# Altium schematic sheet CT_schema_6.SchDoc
size 274 x 160 mm
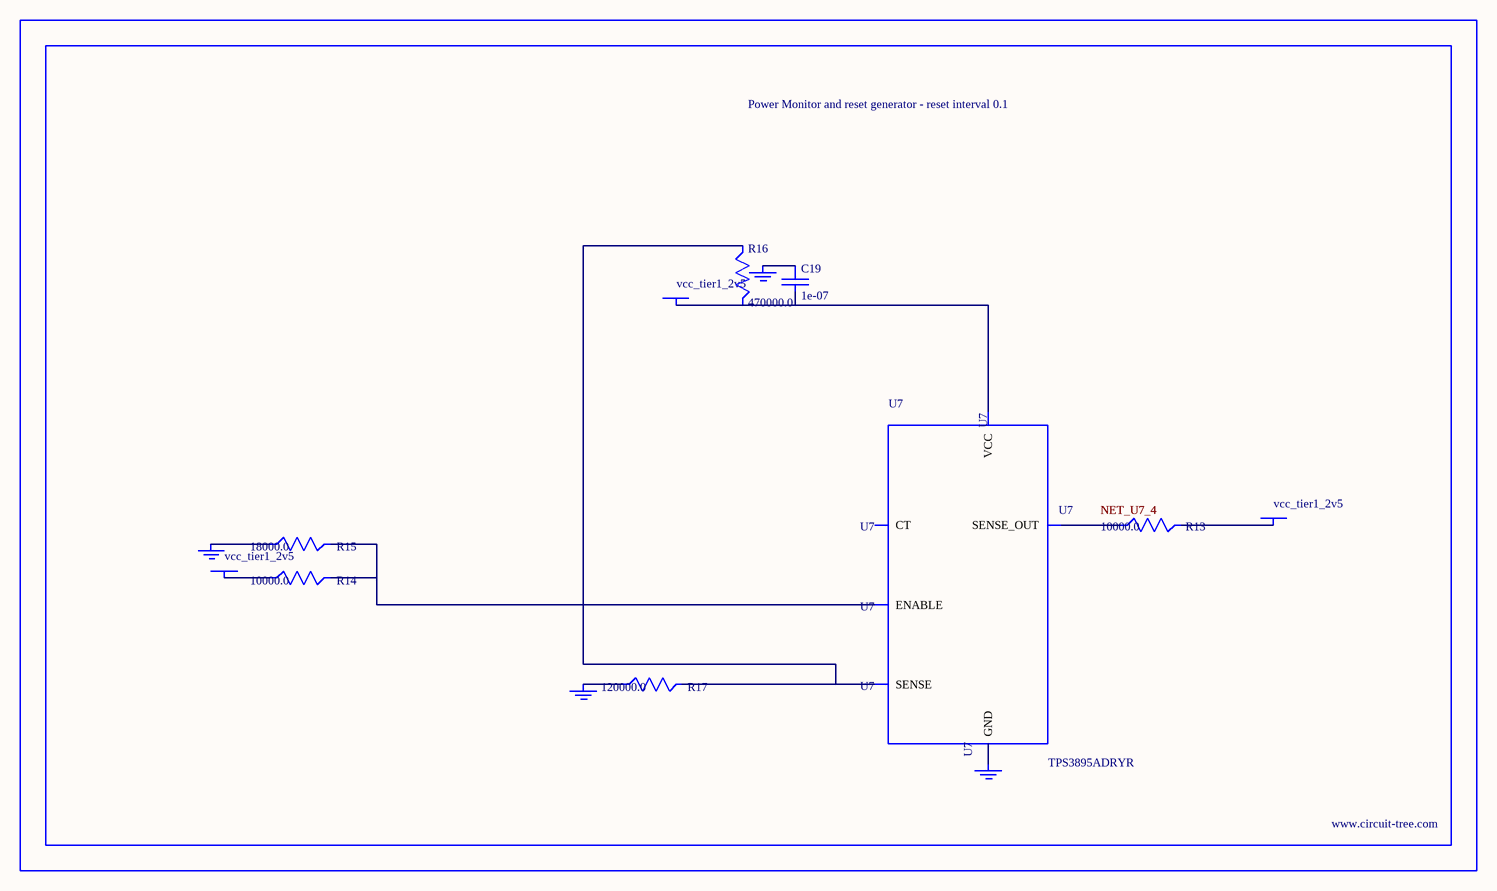
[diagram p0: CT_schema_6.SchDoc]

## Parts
BORDER5  (no value)
C19  1e-07  [C0402]
GND_INSTANCE_5_0  (no value)
GND_INSTANCE_5_1  (no value)
GND_INSTANCE_5_2  (no value)
GND_INSTANCE_5_3  (no value)
POWER_INSTANCE_5_0  vcc_tier1_2v5
POWER_INSTANCE_5_1  vcc_tier1_2v5
POWER_INSTANCE_5_2  vcc_tier1_2v5
R13  10000.0  [R0603]
R14  10000.0  [R0603]
R15  18000.0  [R0603]
R16  470000.0  [R0603]
R17  120000.0  [R0603]
U7  TPS3895ADRYR  [SON-6]

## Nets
NetC19_1: C19.1 GND_INSTANCE_5_2.0(GND)
NetC19_2: C19.2 POWER_INSTANCE_5_2.0(PWR) R16.2 U7.6(VCC)
NetGND_INSTANCE_5_0_0: GND_INSTANCE_5_0.0(GND) R15.1
NetGND_INSTANCE_5_1_0: GND_INSTANCE_5_1.0(GND) R17.1
NetGND_INSTANCE_5_3_0: GND_INSTANCE_5_3.0(GND) U7.2(GND)
NetPOWER_INSTANCE_5_0_0: POWER_INSTANCE_5_0.0(PWR) R14.1
NetPOWER_INSTANCE_5_1_0: POWER_INSTANCE_5_1.0(PWR) R13.2
NetR13_1: R13.1 U7.4(SENSE_OUT)
NetR14_2: R14.2 R15.2 U7.1(ENABLE)
NetR16_1: R16.1 R17.2 U7.3(SENSE)

Not connected (* = marked no-connect by the designer): U7 5(CT)

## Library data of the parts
BORDER5 = BORDER_PAGE5
C19 = C0402C104K3RACTU
GND_INSTANCE_5_0-GND_INSTANCE_5_3 = GND
POWER_INSTANCE_5_0-POWER_INSTANCE_5_2 = PWR
R13 R14 = RC0603JR-0710KL
R15 = RC0603JR-0718KL
R16 = RC0603JR-07470KL
R17 = RC0603JR-07120KL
